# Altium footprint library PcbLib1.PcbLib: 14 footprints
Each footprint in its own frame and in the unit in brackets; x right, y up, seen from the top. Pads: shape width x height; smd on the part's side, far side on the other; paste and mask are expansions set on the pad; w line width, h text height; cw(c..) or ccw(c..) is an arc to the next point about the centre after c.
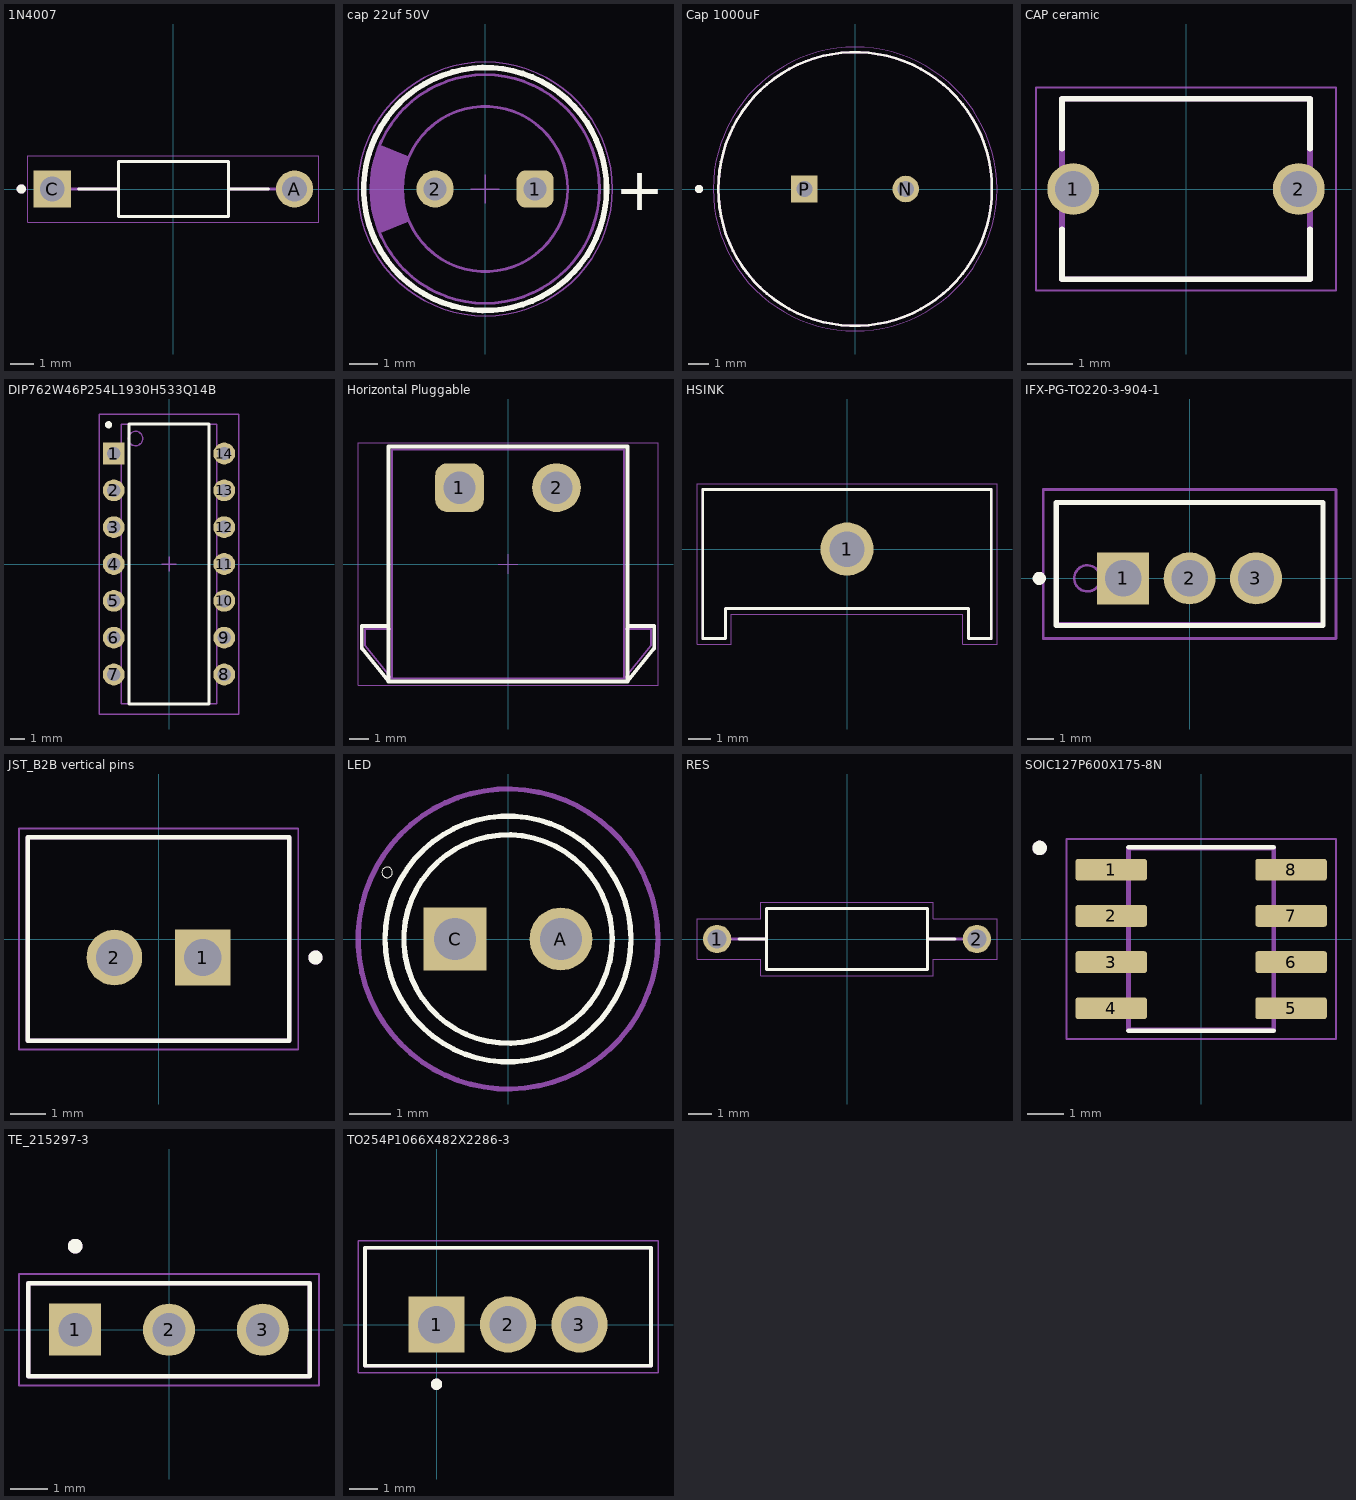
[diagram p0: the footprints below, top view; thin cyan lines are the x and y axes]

## 1N4007 [mm]
height 2.7
pads (2):
  round 1.59 hole 1.06 mask+0.102: A(5.18,0)
  rect 1.59x1.59 / inner round 1.59 / far side rect 1.59x1.59 hole 1.06 mask+0.102: C(-5.18,0)
Top Overlay:
  circle w0.2: c-6.5,0 r0.1
  lines w0.127: -4.065,0 -2.35,0 ; 4.065,0 2.35,0 ; -2.35,0 -2.35,1.175 2.35,1.175 2.35,0 ; -2.35,0 -2.35,-1.175 2.35,-1.175 2.35,0
Mechanical 13:
  circle w0.2: c-6.5,0 r0.1
  lines w0.127: -5.18,0 -2.35,0 ; 5.18,0 2.35,0 ; -2.35,0 -2.35,1.175 2.35,1.175 2.35,0 ; -2.35,0 -2.35,-1.175 2.35,-1.175 2.35,0
Mechanical 15:
  lines w0.05: -6.225,-1.425 -6.225,1.425 6.225,1.425 6.225,-1.425 -6.225,-1.425
3D body "step_temp.STEP": height 2.72, standoff -21.76, extent -5.573,-1.36 5.573,1.36

## cap 22uf 50V [mm] "Aluminum Electrolytic Capacitors, 8x11.5mm"
height 11.5
pads (2):
  rrect50% 1.3x1.3 hole 0.8: 1(1.75,0)
  round 1.3 hole 0.8: 2(-1.75,0)
Top Overlay:
  circle w0.2: c0,0 r4.25
  text "+" at 4.55,-0.75 h1.5
Top 3D Body:
  circle w0.1: c0,0 r2.89
  circle w0.1: c0,0 r4
  region: -3.685,-1.557 -3.762,-1.372 -3.881,-0.99 -3.96,-0.598 -4,-0.2 -4,0.2 -3.96,0.598 -3.881,0.99 -3.762,1.372 -3.685,1.557 -2.662,1.125 -2.662,1.124 -2.715,0.99 -2.8,0.714 -2.858,0.431 -2.886,0.144 -2.886,-0.144 -2.858,-0.431 -2.8,-0.714 -2.715,-0.99 -2.662,-1.124 -2.662,-1.125
Top Courtyard:
  circle w0.05: c0,0 r4.45
  lines w0.05: -0.5,0 0.5,0 ; 0,-0.5 0,0.5
Top Component Outline:
  circle w0.1: c0,0 r2.89
  circle w0.1: c0,0 r4
  region: -3.685,-1.557 -3.762,-1.372 -3.881,-0.99 -3.96,-0.598 -4,-0.2 -4,0.2 -3.96,0.598 -3.881,0.99 -3.762,1.372 -3.685,1.557 -2.662,1.125 -2.662,1.124 -2.715,0.99 -2.8,0.714 -2.858,0.431 -2.886,0.144 -2.886,-0.144 -2.858,-0.431 -2.8,-0.714 -2.715,-0.99 -2.662,-1.124 -2.662,-1.125
3D body "8x11.5x3.5x0.5.stp": height 11.81, standoff -19.91, extent -3.99,-4 4,3.999

## Cap 1000uF [mm]
height 22
pads (2):
  round 1.308 hole 0.8: N(2.5,0)
  rect 1.308x1.308 / inner round 1.308 / far side rect 1.308x1.308 hole 0.8: P(-2.5,0)
Top Overlay:
  circle w0.127: c0,0 r6.75
  circle w0.2: c-7.7,0 r0.1
Mechanical 13:
  circle w0.127: c0,0 r6.75
  circle w0.2: c-7.7,0 r0.1
Mechanical 15:
  circle w0.05: c0,0 r7
3D body "step_temp.STEP": height 22, standoff -20, extent -6.5,-6.25 6,6.25

## CAP ceramic [mm]
pads (2):
  round 1.15 hole 0.8: 1(-2.5,0) 2(2.5,0)
Top Overlay:
  lines w0.127: -2.75,-0.895 -2.75,-2 2.75,-2 2.75,-0.895 ; -2.75,0.895 -2.75,2 2.75,2 2.75,0.895
Mechanical 13:
  lines w0.127: -2.75,-2 2.75,-2 2.75,2 -2.75,2 -2.75,-2
Mechanical 15:
  lines w0.05: -3.325,-2.25 3.325,-2.25 3.325,2.25 -3.325,2.25 -3.325,-2.25
3D body "step_temp.STEP": height 7, standoff -9, extent -2.75,-2 2.75,2

## DIP762W46P254L1930H533Q14B [mm] "DIP,7.62mm lead span,2.54mm pitch;14 pin,6.605mm W X 19.305mm L X 5.33mm H body"
height 5.33
pads (14):
  rect 1.5x1.5 hole 0.9 paste-2539.97 mask+0: 1(-3.81,7.62)
  round 1.5 hole 0.9 paste-2539.97 mask+0: 2(-3.81,5.08) 3(-3.81,2.54) 4(-3.81,0) 5(-3.81,-2.54) 6(-3.81,-5.08) 7(-3.81,-7.62) 8(3.81,-7.62) 9(3.81,-5.08) 10(3.81,-2.54) 11(3.81,0) 12(3.81,2.54) 13(3.81,5.08) 14(3.81,7.62)
Top Overlay:
  circle w0.25: c-4.166,9.601 r0.125
  lines w0.2: -2.75,-9.65 -2.75,9.65 2.75,9.65 2.75,-9.65 -2.75,-9.65
Top Courtyard:
  text ".DESIGNATOR" at 0,0 h1.2
Mechanical 13:
  circle w0.1: c-2.302,8.652 r0.5
  lines w0.1: -3.303,-9.653 3.303,-9.653 3.303,9.653 -3.303,9.653 -3.303,-9.653
Mechanical 15:
  lines w0.1: -0.5,0 0.5,0 ; 0,-0.5 0,0.5 ; -4.81,-10.345 4.81,-10.345 4.81,10.345 -4.81,10.345 -4.81,-10.345
3D body "IRS2453DPBF.STEP": height 5.33, standoff -3.49, extent -3.956,-9.652 3.957,9.653

## Horizontal Pluggable [mm] "5,08mm - PCB Header Horizontal Entry with Plastic Latches - 02p"
height 8.9
pads (2):
  rrect50% 2.55x2.55 hole 1.7: 1(-2.54,4)
  round 2.55 hole 1.7: 2(2.54,4)
Top Overlay:
  lines w0.2: -6.255,-3.25 -7.655,-3.25 -7.655,-4.421 -6.255,-6.15 ; 6.255,-3.25 7.655,-3.25 7.655,-4.421 6.255,-6.15 ; -6.255,-6.15 6.255,-6.15 ; -6.255,-6.15 -6.255,6.15 6.255,6.15 6.255,-6.15
Top 3D Body:
  lines w0.1: -6.08,-3.411 -7.48,-3.411 -7.48,-4.271 -6.08,-6 ; 6.08,-3.411 7.48,-3.411 7.48,-4.271 6.08,-6 ; -6.08,-6 6.08,-6 ; -6.08,-6 -6.08,6 6.08,6 6.08,-6
Top Courtyard:
  lines w0.05: -7.855,-6.35 7.855,-6.35 7.855,6.35 -7.855,6.35 -7.855,-6.35
Top Component Outline:
  lines w0.1: -6.08,-3.411 -7.48,-3.411 -7.48,-4.271 -6.08,-6 ; 6.08,-3.411 7.48,-3.411 7.48,-4.271 6.08,-6 ; -6.08,-6 -6.08,6 6.08,6 6.08,-6 ; -6.08,-6 6.08,-6
Top Component Center:
  lines w0.05: -0.5,0 0.5,0 ; 0,-0.5 0,0.5
3D body "691305540002.stp": height 8.63, standoff -3.97, extent -7.48,-6 7.48,6

## HSINK [mm] "TO_220"
height 25
pads (1):
  round 2.325 hole 1.55: 1(0,0)
Top Overlay:
  lines w0.127: 6.3,-3.9 5.3,-3.9 5.3,-2.6 -5.3,-2.6 -5.3,-3.9 -6.3,-3.9 -6.3,2.6 6.3,2.6 6.3,-3.87
Mechanical 13:
  lines w0.127: 6.3,-3.9 5.3,-3.9 5.3,-2.6 -5.3,-2.6 -5.3,-3.9 -6.3,-3.9 -6.3,2.6 6.3,2.6 6.3,-3.87
Mechanical 15:
  lines w0.05: -6.55,-4.15 -6.55,2.85 6.55,2.85 6.55,-4.15 5.05,-4.15 5.05,-2.85 -5.05,-2.85 -5.05,-4.15 -6.55,-4.15
3D body "step_temp.STEP": height 25, standoff -3.5, extent -6.3,-3.9 6.3,2.6

## IFX-PG-TO220-3-904-1 [mm] "TO,flange mount,2.54 mm pitch, 3 pin, 10.16 mm L X 4.57 mm W X 20.56 mm H body"
height 20.56
pads (3):
  rect 1.99x1.99 hole 1.39 paste-2539.97 mask+0: 1(-2.54,0)
  round 1.99 hole 1.39 paste-2539.97 mask+0: 2(0,0) 3(2.54,0)
Top Overlay:
  circle w0.25: c-5.75,0 r0.125
  lines w0.2: -5.1,-1.8 -5.1,2.9 5.1,2.9 5.1,-1.8 -5.1,-1.8
Top Courtyard:
  text ".DESIGNATOR" at 0,0 h1.2
Mechanical 13:
  circle w0.1: c-3.912,0 r0.5
  lines w0.1: -5.08,-1.71 -5.08,2.86 5.08,2.86 5.08,-1.71 -5.08,-1.71
Mechanical 15:
  lines w0.1: -0.5,0 0.5,0 ; 0,-0.5 0,0.5 ; -5.6,-2.3 -5.6,3.4 5.6,3.4 5.6,-2.3 -5.6,-2.3
3D body "PG-TO220-3-904_Z8B00198139_V06_3D.stp": height 19.84, standoff -10.77, extent -5.156,-1.72 5.156,2.86

## JST_B2B vertical pins [mm]
height 7
pads (2):
  rect 1.575x1.575 / inner round 1.575 / far side rect 1.575x1.575 hole 1.05: 1(1.25,-0.525)
  round 1.575 hole 1.05: 2(-1.25,-0.525)
Top Overlay:
  circle w0.2: c4.44,-0.525 r0.1
  lines w0.127: -3.7,-2.875 3.7,-2.875 3.7,2.875 -3.7,2.875 -3.7,-2.875
Mechanical 13:
  circle w0.2: c4.44,-0.525 r0.1
  lines w0.127: -3.7,-2.875 3.7,-2.875 3.7,2.875 -3.7,2.875 -3.7,-2.875
Mechanical 15:
  lines w0.05: -3.95,-3.125 -3.95,3.125 3.95,3.125 3.95,-3.125 -3.95,-3.125
3D body "step_temp.STEP": height 7, standoff -3.4, extent -3.7,-2.875 3.7,2.875

## LED [mm] "LED_WP7113SEC/J3"
pads (2):
  round 1.508 hole 1: A(1.27,0)
  rect 1.508x1.508 hole 1: C(-1.27,0)
Top Overlay:
  circle w0.127: c0,0 r2.95
  circle w0.127: c0,0 r2.5
  circle w0: c-2.9,1.6 r0.127
Mechanical 15:
  circle w0.127: c0,0 r3.6
3D body "WP7113SEC_J3.STEP": height 9.6, standoff -26, extent -2.492,-2.9 2.942,3

## RES [mm]
height 2.6
pads (2):
  round 1.2 hole 0.8: 1(-5.5,0) 2(5.5,0)
Top Overlay:
  lines w0.127: -4.58,0 -3.4,0 ; 4.58,0 3.4,0 ; -3.4,0 -3.4,-1.3 3.4,-1.3 3.4,0 ; -3.4,0 -3.4,1.3 3.4,1.3 3.4,0
Mechanical 13:
  lines w0.127: -4.9,0 -3.4,0 ; 4.9,0 3.4,0 ; -3.4,0 -3.4,-1.3 3.4,-1.3 3.4,0 ; -3.4,0 -3.4,1.3 3.4,1.3 3.4,0
Mechanical 15:
  lines w0.05: -6.35,-0.85 -6.35,0.85 -3.65,0.85 -3.65,1.55 3.65,1.55 3.65,0.85 6.35,0.85 6.35,-0.85 3.65,-0.85 3.65,-1.55 -3.65,-1.55 -3.65,-0.85 -6.35,-0.85
3D body "step_temp.STEP": height 2.6, standoff -25.53, extent -5.775,-1.3 5.775,1.3

## SOIC127P600X175-8N [mm]
height 1.75
pads (8):
  rrect25% 1.97x0.6 smd paste+0 mask+0.102: 1(-2.475,1.905) 2(-2.475,0.635) 3(-2.475,-0.635) 4(-2.475,-1.905) 5(2.475,-1.905) 6(2.475,-0.635) 7(2.475,0.635) 8(2.475,1.905)
Top Overlay:
  circle w0.2: c-4.445,2.505 r0.1
  lines w0.127: -2,-2.525 2,-2.525 ; -2,2.525 2,2.525
Mechanical 13:
  circle w0.2: c-4.445,2.505 r0.1
  lines w0.127: -2,-2.5 2,-2.5 2,2.5 -2,2.5 -2,-2.5
Mechanical 15:
  lines w0.05: -3.71,-2.75 3.71,-2.75 3.71,2.75 -3.71,2.75 -3.71,-2.75
3D body "ACS712ELCTR-05B-T.STEP": height 1.75, standoff 0, extent -3,-2.45 3,2.45

## TE_215297-3 [mm]
pads (3):
  rect 1.408x1.408 hole 0.9: 1(-2.54,0)
  round 1.408 hole 0.9: 2(0,0) 3(2.54,0)
Top Overlay:
  circle w0.2: c-2.54,2.26 r0.1
  lines w0.127: -3.81,-1.26 3.81,-1.26 3.81,1.26 -3.81,1.26 -3.81,-1.26
Mechanical 13:
  circle w0.2: c-2.54,2.26 r0.1
  lines w0.127: -3.81,-1.26 3.81,-1.26 3.81,1.26 -3.81,1.26 -3.81,-1.26
Mechanical 15:
  lines w0.05: -4.06,-1.51 4.06,-1.51 4.06,1.51 -4.06,1.51 -4.06,-1.51
3D body "step_temp.STEP": height 7.62, standoff -2.38, extent -3.81,-1.27 3.81,1.25

## TO254P1066X482X2286-3 [mm]
height 22.86
pads (3):
  rect 2x2 / inner round 2 / far side rect 2x2 hole 1.33: 1(0,0)
  round 2 hole 1.33: 2(2.54,0) 3(5.08,0)
Top Overlay:
  circle w0.2: c0,-2.123 r0.1
  lines w0.127: -2.54,-1.468 7.62,-1.468 7.62,2.722 -2.54,2.722 -2.54,-1.468
Mechanical 13:
  circle w0.2: c0,-2.123 r0.1
  lines w0.127: -2.54,-1.468 7.62,-1.468 7.62,2.722 -2.54,2.722 -2.54,-1.468
Mechanical 15:
  lines w0.05: -2.79,-1.718 7.87,-1.718 7.87,2.972 -2.79,2.972 -2.79,-1.718
3D body "step_temp.STEP": height 20.4, standoff -9.94, extent -2.54,-1.651 7.62,2.699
